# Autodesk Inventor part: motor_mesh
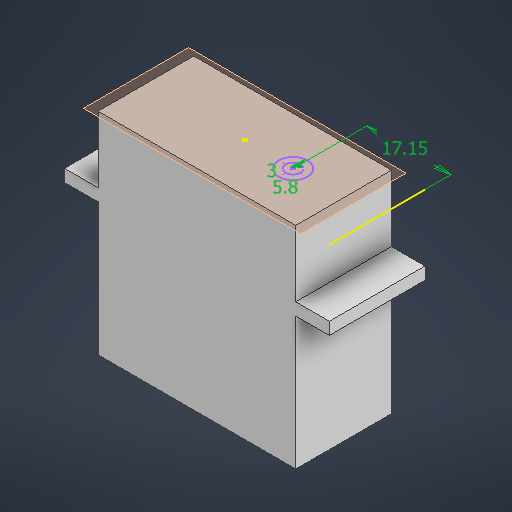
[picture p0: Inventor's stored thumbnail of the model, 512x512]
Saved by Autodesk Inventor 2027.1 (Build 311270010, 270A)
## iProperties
Created: 2026-11
Part Number: motor_mesh
Material: Generic
Document SubType Name: Modeling
Designer: djshs
Density: 1 g/cm^3
Appearance: Default
Author: djshs
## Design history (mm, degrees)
sketch "스케치1"
  geometry: L1 (20.15, 9.75)-(-20.15, 9.75); L2 (-20.15, 9.75)-(-20.15, -9.75); L3 (-20.15, -9.75)-(20.15, -9.75); L4 (20.15, -9.75)-(20.15, 9.75); L5 (20.15, 9.75)-(-20.15, -9.75); L6 (-20.15, 9.75)-(20.15, -9.75); 1 further point
  constraints: 12 end point, 2 midpoint, 2 parallel, 1 horizontal, 1 perpendicular
  dimensions: "d0" = 40.3 distance of L3.end L2.end; "d1" = 19.5 distance of L2.end L1.end
extrude "돌출1" new body sketch "스케치1" distance "d2" = 27; taper "d3" = 0 deg
sketch "스케치2"
  geometry: L1 (-27, -9.75)-(27, -9.75); L2 (27, -9.75)-(27, 9.75); L3 (27, 9.75)-(-27, 9.75); L4 (-27, 9.75)-(-27, -9.75); L5 (-27, -9.75)-(27, 9.75); L6 (27, -9.75)-(-27, 9.75); 1 further point
  constraints: 12 end point, 2 midpoint, 2 parallel, 1 horizontal, 1 perpendicular
  dimensions: "d4" = 54 distance of L3.end L2.end; "d5" = 19.5 distance of L2.end L1.end
extrude "돌출2" join sketch "스케치2" distance "d6" = 2.5; taper "d7" = 0 deg
sketch "스케치3"
  geometry: L1 (-27, -9.75)-(-20.15, -9.75) reference; L2 (20.15, 9.75)-(-20.15, 9.75); L3 (-20.15, 9.75)-(-20.15, -9.75); L4 (-20.15, -9.75)-(20.15, -9.75); L5 (20.15, -9.75)-(20.15, 9.75); L6 (20.15, 9.75)-(-20.15, -9.75); L7 (-20.15, 9.75)-(20.15, -9.75); 2 further points
  constraints: 12 end point, 2 midpoint, 2 parallel, 1 horizontal, 1 perpendicular, 1 point on line
  dimensions: "d8" = 40.3 distance of L4.end L3.end
extrude "돌출3" join sketch "스케치3" distance "d9" = 13.5; taper "d10" = 0 deg
node "작업 평면1"
sketch "스케치4"
  geometry: L1 (27, -9.75)-(27, 9.75) reference; C1 r 2.9 at (9.85, 0); C2 r 1.5 at (9.85, 0); 2 further points
  constraints: 2 centre point, 2 coincident
  dimensions: "d12" = 17.15 distance from line of L1 point (9.85, 0); "d13" = 5.8 diameter of C1; "d14" = 3 diameter of C2
node "솔리드1"
other parameters: "d11" = 0
